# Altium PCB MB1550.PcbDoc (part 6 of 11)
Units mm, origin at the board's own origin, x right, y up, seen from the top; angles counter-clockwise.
Board outline 154.81 x 170.69 mm, 6 copper layers (Top Layer, Signal Layer 1, Signal Layer 2, Signal Layer 3, Signal Layer 4, Bottom Layer), stack 1.49 mm thick; 810 components, 633 nets, 2973 pads, 2150 vias.
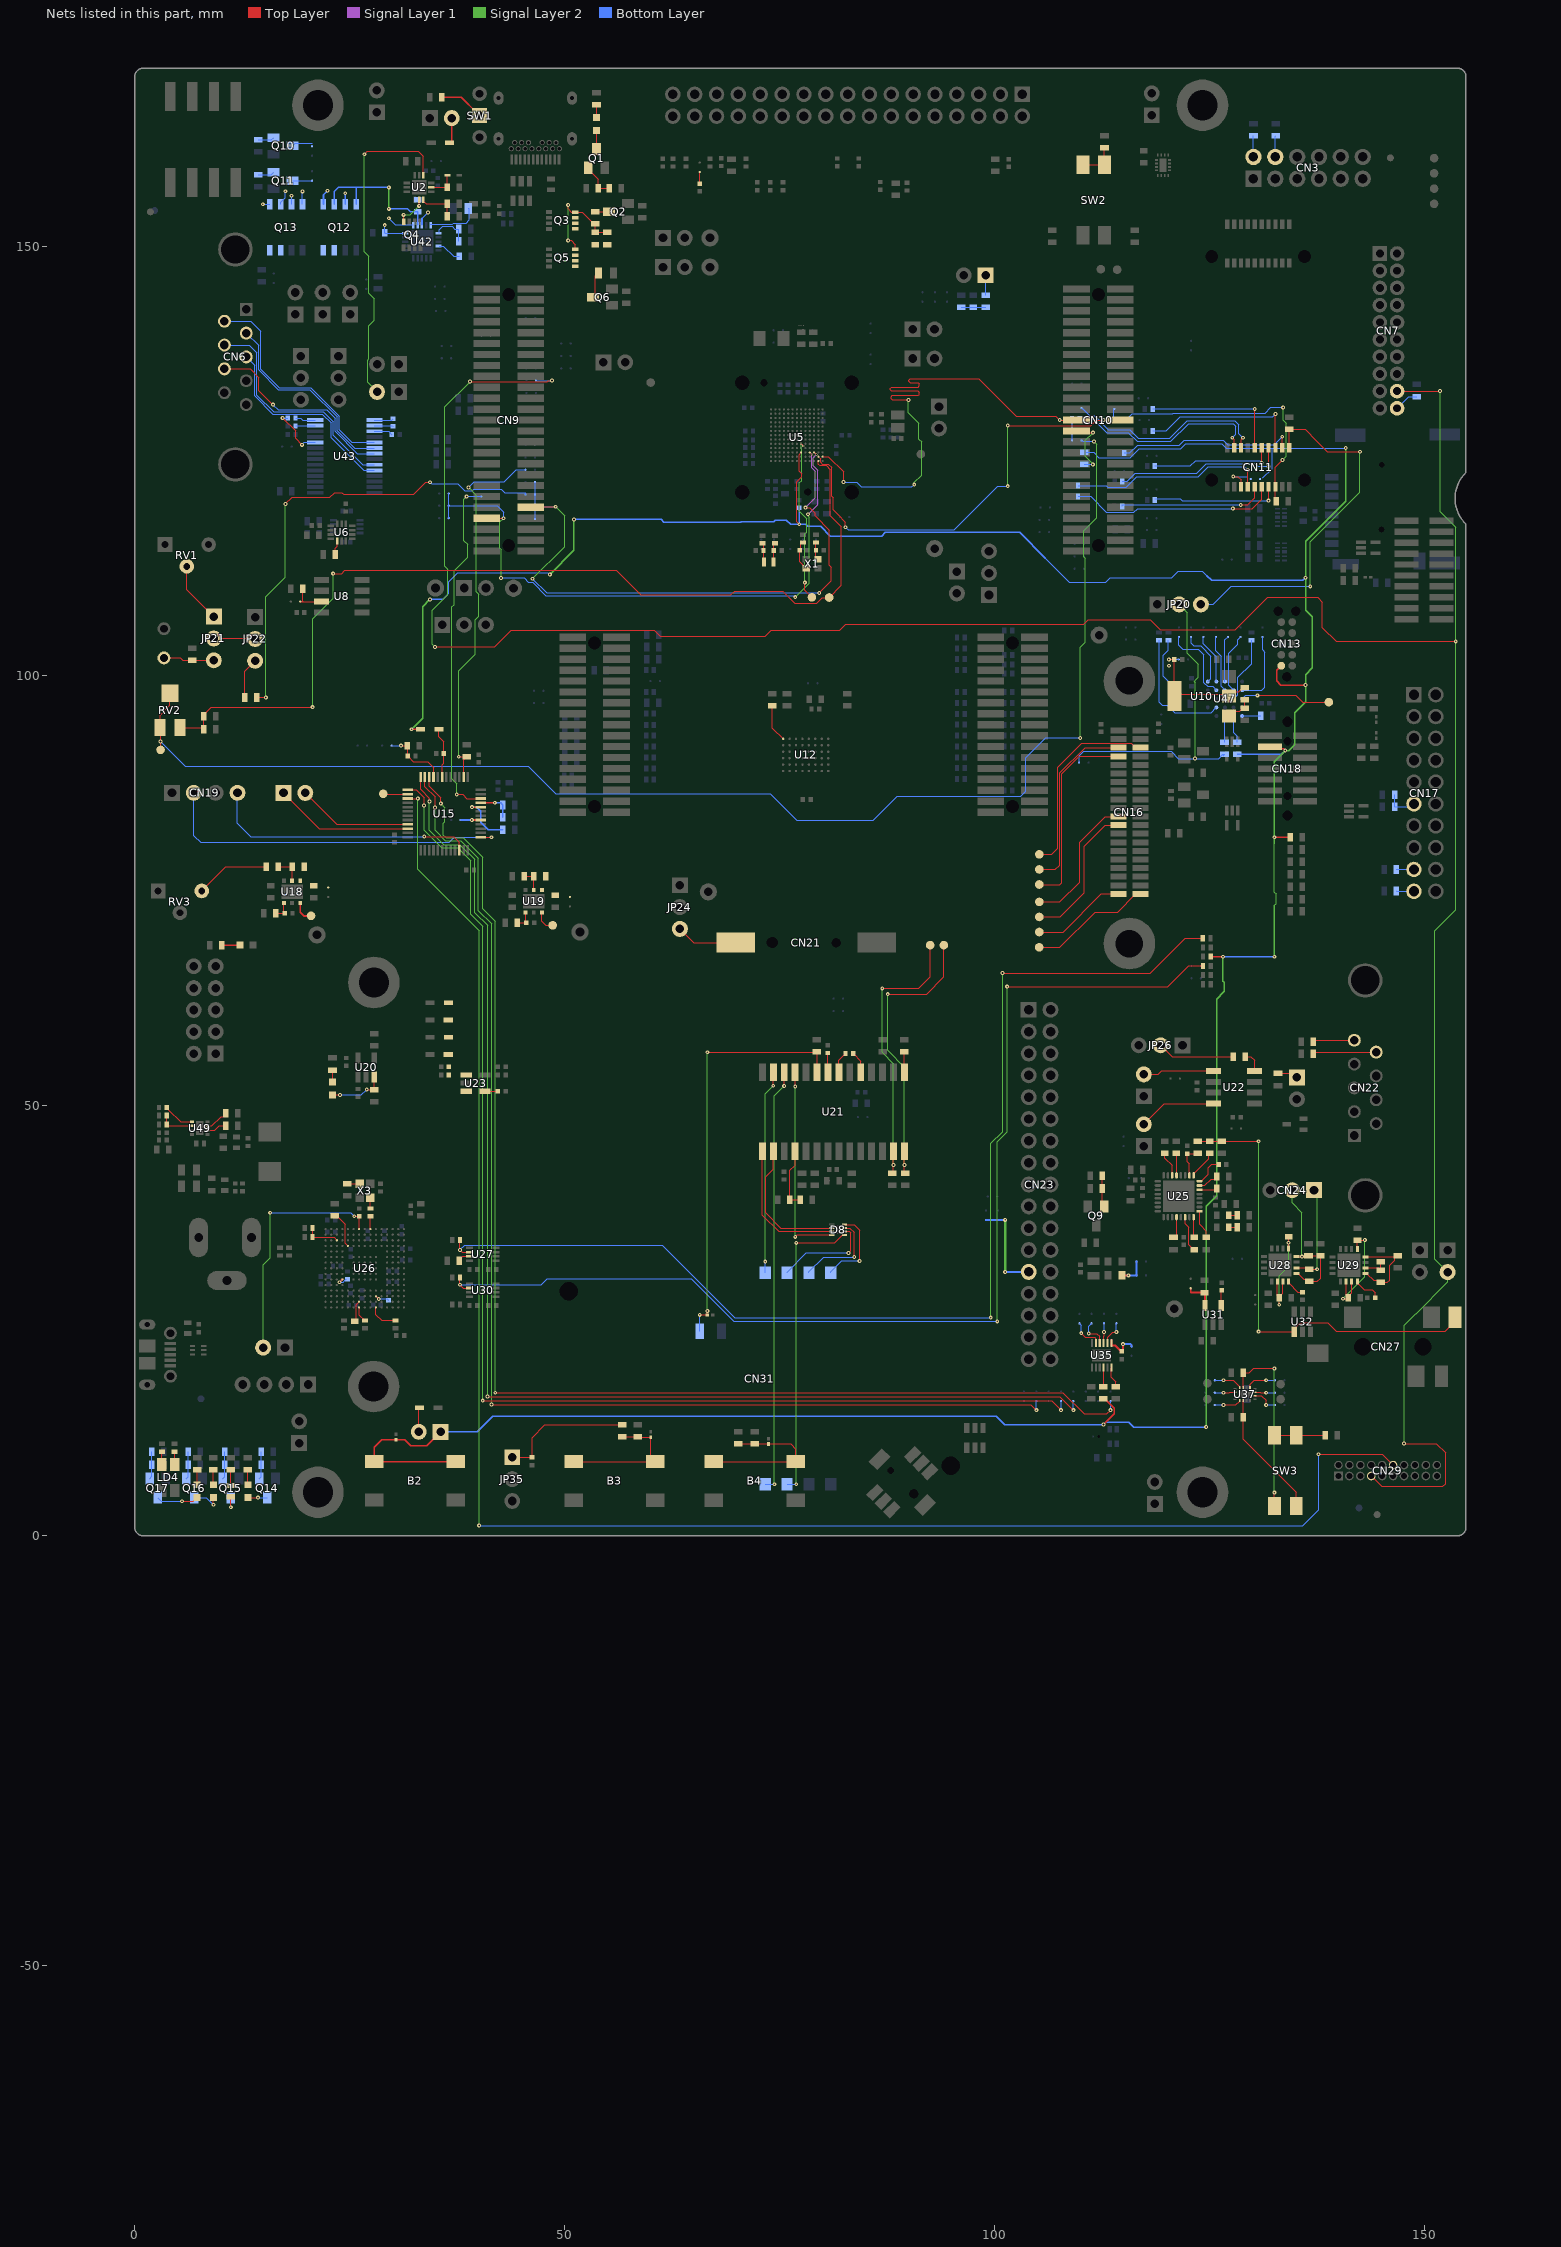
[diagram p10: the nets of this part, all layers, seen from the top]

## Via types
v1: diameter 0.45, hole 0.2, Top Layer to Bottom Layer, tented both sides, 1777 vias
v2: diameter 0.25, hole 0.1, Top Layer to Signal Layer 1, tented top, 344 vias
v3: diameter 0.25, hole 0.1, Signal Layer 1 to Signal Layer 2, 29 vias

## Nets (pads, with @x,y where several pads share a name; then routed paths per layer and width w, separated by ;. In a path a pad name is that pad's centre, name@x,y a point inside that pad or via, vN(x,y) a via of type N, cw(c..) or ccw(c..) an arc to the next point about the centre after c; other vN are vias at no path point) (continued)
MDF1_SDIN5: CN7.19 CN29.7 JP31.2 SB41.2 | length 321
  Top Layer w0.1: CN7.19@146.8,133.128 148.1,133.128
  Top Layer w0.12: v1(34.925,103.375) 41.875,103.375 43.803,105.303 60.422,105.303 61.125,104.6 73.3,104.6 73.995,105.295 81.97,105.295 82.665,105.99 110.365,105.99 110.9,106.525 118.1,106.525 119.27,105.355 127.976,105.355 131.783,109.162 137.563,109.162 138.125,108.6 138.125,105.627 139.727,104.025 v1(153.625,104.025) ; v1(38.99,134.24) 47.99,134.24 48.1,134.35 v1(48.525,134.35) ; CN29.7@143.795,6.965 144.992,5.768 152.128,5.768 152.44,6.08 152.44,9.646 151.343,10.743 v1(147.604,10.743) ; 148.1,133.128 v1(151.8,133.128)
  Signal Layer 2 w0.12: v1(34.925,103.375) 34.625,103.675 34.625,107.65 36.416,109.441 36.416,112.409 36.075,112.75 36.075,131.325 v1(38.99,134.24) ; v1@147.605,10.742 147.605,24.476 148.984,25.855 149.003,25.855 152.675,29.527 JP31.2@152.675,30.68 151.2,32.155 151.2,70.4 153.625,72.825 v1(153.625,104.025) 153.625,117.3 151.8,119.125 v1(151.8,133.128)
  Bottom Layer w0.12: SB41.2@46.65,134.35 v1(48.525,134.35)
MEMS_1-2_SEL: R118.1 SW3.1 U37.3 | length 21.5
  Top Layer w0.12: U37.3@128.9,17.275 R118.1@128.9,18.975 129.625,18.975 130.12,19.47 v1(132.53,19.47) ; SW3.1@132.53,3.475 v1(132.53,5.03)
  Signal Layer 2 w0.12: v1(132.53,5.03) v1(132.53,19.47)
MEMS_3-4_SEL: R122.1 SW3.2 U37.10 | length 14.8
  Top Layer w0.12: U37.10@128.9,15.725 R122.1@128.9,13.8 128.9,11.225 135.07,5.055 SW3.2@135.07,3.475
MEMS_LED: CN29.12 U15.15 | length 202.7
  Top Layer w0.12: U15.15@31.748,85.75 v1(32.925,85.75) ; v1(137.664,9.493) 145.077,9.493 CN29.12@146.335,8.235
  Signal Layer 2 w0.12: v1(32.925,85.75) 32.925,77.525 40.05,70.4 v1(40.05,1.2)
  Bottom Layer w0.12: v1(40.05,1.2) 135.843,1.2 137.664,3.021 v1(137.664,9.493)
MFX_I2C_ADDR: R231.2 R233.2 U15.45 | length 4.1
  Top Layer w0.2: U15.45@40.248,85.25 v1(41.875,85.25)
  Bottom Layer w0.2: v1(41.875,85.25) 42.55,85.25 R231.2@42.8,85 R233.2@42.8,83.575
MFX_IRQ_OUT: SB70.2 U15.46 | length 40.7
  Top Layer w0.12: v1(37.45,86.225) 38.125,86.225 38.6,85.75 U15.46@40.248,85.75
  Signal Layer 2 w0.12: v1(37.45,86.225) 37.45,87.45 36.865,88.035 36.865,108.042 37.13,108.307 37.13,112.23 38.702,113.802 38.702,115.29 38.25,115.742 38.25,120.525 v1(38.6,120.875)
  Bottom Layer w0.12: v1(38.6,120.875) SB70.2@40.3,120.875
MFX_LOOP: TP19.1 U15.14 | length 2.9
  Top Layer w0.12: TP19.1@28.9,86.3 28.95,86.25 U15.14@31.748,86.25
MFX_SWCLK: CN19.2 U15.37 | length 41.4
  Top Layer w0.12: U15.37@40.248,81.25 v1(41.475,81.25)
  Bottom Layer w0.12: CN19.2@6.869,86.411 6.869,81.431 7.65,80.65 36.575,80.65 37.175,81.25 v1(41.475,81.25)
MFX_SWDIO: CN19.4 U15.34 | length 31.2
  Top Layer w0.12: v1(33.675,81.325) 37.075,81.325 37.748,80.652 U15.34@37.748,79.75
  Bottom Layer w0.12: CN19.4@11.949,86.411 11.949,82.851 13.475,81.325 v1(33.675,81.325)
MFX_TSC_XN: SB142.2 U15.11 | length 141.9
  Top Layer w0.12: U15.11@33.748,88.25 33.748,87.127 34.925,85.95 v1(34.925,84.7) ; v1(41.5,15.275) 104.2,15.275 v1(104.85,14.625)
  Signal Layer 2 w0.12: v1(34.925,84.7) 34.925,82.05 36.125,80.85 37.925,80.85 39.975,78.8 39.975,72.725 41.5,71.2 v1(41.5,15.275)
  Bottom Layer w0.12: v1(104.85,14.625) SB142.2@104.85,15.675
MFX_TSC_XP: SB136.2 U15.10 | length 149.9
  Top Layer w0.12: U15.10@34.248,88.25 34.248,87.202 35.6,85.85 v1(35.6,85.175) ; v1(41.925,16.65) 107.925,16.65 110.4,14.175 113.025,14.175 v1(113.475,14.625)
  Signal Layer 2 w0.12: v1(35.6,85.175) 36.08,84.695 36.08,83.052 35.895,82.867 35.895,81.505 36.2,81.2 38.223,81.2 40.475,78.948 40.475,72.925 41.925,71.475 v1(41.925,16.65)
  Bottom Layer w0.12: v1(113.475,14.625) SB136.2@113.475,15.675
MFX_TSC_YN: SB140.2 U15.13 | length 145.1
  Top Layer w0.12: U15.13@31.748,86.75 32.725,86.75 33.65,85.825 v1(33.65,84.95) ; v1(40.475,15.725) 106.625,15.725 v1(107.725,14.625)
  Signal Layer 2 w0.12: v1(33.65,84.95) 33.65,82.075 35.725,80 37.575,80 39.088,78.487 39.088,72.262 40.475,70.875 v1(40.475,15.725)
  Bottom Layer w0.12: v1(107.725,14.625) SB140.2@107.725,15.675
MFX_TSC_YP: SB139.2 U15.12 | length 146.2
  Top Layer w0.12: U15.12@33.248,88.25 33.248,86.827 34.275,85.8 v1(34.275,85.4) ; v1(41.025,16.2) 107.575,16.2 v1(109.15,14.625)
  Signal Layer 2 w0.12: v1(34.275,85.4) 34.275,82.075 35.95,80.4 37.8,80.4 39.538,78.662 39.538,72.487 41.025,71 v1(41.025,16.2)
  Bottom Layer w0.12: v1(109.15,14.625) SB139.2@109.15,15.675
MFX_WAKEUP: R45.2 SB60.2 U15.2 | length 43.7
  Top Layer w0.12: v1(37.675,90.6) R45.2@38.6,90.6 38.248,90.248 U15.2@38.248,88.25
  Signal Layer 2 w0.12: v1(37.675,90.6) 37.675,100.625 39.58,102.53 39.58,106.534 39.981,106.934 39.981,109.527 39.74,109.767 39.74,121.01 v1(38.825,121.925)
  Bottom Layer w0.12: v1(38.825,121.925) 39.475,122.575 42.975,122.575 44.375,123.975 SB60.2@45.45,123.975
MIC_IN: C66.1 CN27.2 R83.1 R84.2 U32.1 | length 54.1
  Top Layer w0.12: R83.1@123.6,45.9 C66.1@125,45.9 R84.2@126.4,45.9 v1(130.7,45.9) ; v1(130.7,23.75) U32.1@134.85,23.75 134.85,24.1 135.55,24.8 138.725,24.8 139.725,23.8 152.425,23.8 153.55,24.925 CN27.2@153.55,25.45
  Signal Layer 2 w0.12: v1(130.7,23.75) v1(130.7,45.9)
NetB3_3: B3.3 B3.4 R123.2 R124.2 U39.1 | length 15.9
  Top Layer w0.12: B3.4@51.05,8.641 B3.3@60.55,8.641 60,9.191 U39.1@60,11.487 58.513,11.487 R124.2@58.5,11.5 R123.2@56.7,11.5
NetB4_3: B4.3 B4.4 R125.2 R126.2 U41.1 | length 17.9
  Top Layer w0.12: B4.4@67.35,8.641 B4.3@76.85,8.641 76.85,10.1 76.263,10.687 U41.1@73.7,10.687 72.113,10.687 R126.2@72.1,10.7 R125.2@70.2,10.7
NetC16_2: C16.2 SB1.2 | length 1.4
  Top Layer w0.12: C16.2@65.7,157.25 SB1.2@65.7,158.6
NetC17_1: C17.1 D2.2 U2.8 | length 3.2
  Top Layer w0.12: U2.8@34.5,156.825 C17.1@36.325,156.825 36.325,158.175 D2.2@36.375,158.225
NetC19_1: C19.1 Q3.4 Q5.4 R14.2 R18.1 | length 12.5
  Top Layer w0.12: v1(50.4,150.65) 50.75,150.65 51.225,150.175 Q5.4@51.225,149.6 ; v1(50.4,154.775) 50.4,154.325 50.775,153.95 Q3.4@51.225,153.95 52.025,153.95 R14.2@53.375,152.6 ; R14.2@53.35,152.6 R14.2@53.375,152.6 ; R18.1@54.95,151.575 C19.1@53.55,151.575 R14.2@53.55,152.6 R14.2@53.375,152.6
  Signal Layer 2 w0.12: v1(50.4,150.65) v1(50.4,154.775)
NetC19_2: C19.2 Q3.1 Q3.2 Q3.3 Q5.1 Q5.2 Q5.3 R18.2
NetC34_2: C34.2 R35.2 SB104.1 U10.2 U10.4 | length 14.9
  Top Layer w0.12: v1(120.255,101.925) C34.2@120.9,101.925 U10.4@120.9,97.65 121.125,97.875 127.025,97.875 U10.2@127.25,97.65 127.75,98.15 128.4,98.15 128.875,98.625 R35.2@129.1,98.625
  Bottom Layer w0.12: v1(120.255,101.925) SB104.1@121.4,101.925
  other v1: 120.275,101.187
NetC39_2: C39.2 C42.2 SB110.2 U15.9 | length 7.7
  Top Layer w0.12: v1(30.975,91.9) C39.2@31.7,91.9 31.75,91.85 C42.2@31.75,90.7 32.4,90.05 34.05,90.05 34.748,89.352 U15.9@34.748,88.25
  Bottom Layer w0.12: SB110.2@29.875,91.9 v1(30.975,91.9)
NetC40_1: C40.1 D3.1 U15.7 | length 5.9
  Top Layer w0.12: D3.1@35.37,93.8 35.37,92.93 35.95,92.35 C40.1@35.95,91 35.95,89.85 35.748,89.648 U15.7@35.748,88.25
NetC47_2: C47.2 R56.2 SB3.1 U18.4
NetC49_2: C49.2 R59.2 SB4.1 U19.4
NetC50_1: C50.1 R64.2 U18.1 | length 2.3
  Top Layer w0.12: R64.2@16.4,72.4 C50.1@17.45,72.4 17.35,72.5 U18.1@17.35,73.6
NetC51_1: C51.1 R65.2 U19.1 | length 2.3
  Top Layer w0.12: R65.2@44.5,71.3 C51.1@45.55,71.3 45.45,71.4 U19.1@45.45,72.5
NetC52_1: C52.1 U21.8 | length 2.2
  Top Layer w0.13: C52.1@80.6,56.15 80.615,56.135 U21.8@80.615,53.931
NetC53_1: C53.1 U21.5 | length 2.5
  Top Layer w0.13: C53.1@83.55,56.1 84.425,55.225 U21.5@84.425,53.931
NetC53_2: C53.2 U21.7 | length 2.5
  Top Layer w0.13: U21.7@81.885,53.931 81.885,55.285 82.65,56.05 C53.2@82.65,56.1
NetC55_1: C55.1 C57.2 D4.2 D5.2 D6.2 D7.2 U23.1 U23.3
NetC62_2: C62.2 U23.4 | length 1.5
  Top Layer w0.12: U23.4@40.75,51.7 C62.2@42.225,51.7
NetC65_1: C65.1 U25.22 | length 2.9
  Top Layer w0.12: C65.1@119.8,44.5 119.8,43.925 120.65,43.075 U25.22@120.65,41.925
NetC66_2: C66.2 U25.17 | length 3.3
  Top Layer w0.12: U25.17@123.15,41.925 123.15,42.1 124.9,43.85 124.9,44.4 C66.2@125,44.5
NetC67_1: C67.1 U25.21 | length 2.6
  Top Layer w0.12: C67.1@121.1,44.5 121.15,44.45 U25.21@121.15,41.925
NetC68_1: C68.1 R83.2 U25.18 | length 3.8
  Top Layer w0.12: U25.18@122.65,41.925 122.65,43.25 122.4,43.5 C68.1@122.4,44.45 123.55,44.45 R83.2@123.6,44.5
NetC69_2: C69.2 U25.16 | length 3.5
  Top Layer w0.12: U25.16@123.825,41.25 124.025,41.25 124.85,42.075 124.85,42.8 125.25,43.2 C69.2@126.05,43.2
NetC72_2: C72.2 U25.15 | length 2.6
  Top Layer w0.12: U25.15@123.825,40.75 124.45,40.75 125.175,41.475 125.8,41.475 C72.2@125.8,41.8
NetC76_2: C76.2 U25.14 | length 2
  Top Layer w0.12: U25.14@123.825,40.25 125.65,40.25 C76.2@125.8,40.4
NetC83_1: C83.1 JP32.2 U26.J1 | length 28
  Top Layer w0.1: v1(25.525,37.175) C83.1@26.1,37.175 U26.J1@26.1,35.675
  Signal Layer 2 w0.12: JP32.2@14.93,21.9 14.93,31.505 15.75,32.325 v1(15.75,37.575)
  Bottom Layer w0.1: 19.325,37.575 25.125,37.575 v1(25.525,37.175)
  Bottom Layer w0.12: v1(15.75,37.575) 19.325,37.575
NetC84_1: C84.1 R98.2 | length 1
  Top Layer w0.12: C84.1@127.2,37.3 R98.2@128.2,37.3
NetC85_2: C85.2 C101.1 U28.2 U28.3 U28.9 | length 14
  Top Layer w0.12: U28.2@132.875,29.6 132.875,27.925 C101.1@133.1,27.7 ; v1(133.1,26.875) C101.1@133.1,27.7 ; U28.3@133.525,29.6 133.525,28.225 133.1,27.8 C101.1@133.1,27.7 ; U28.9@134.175,33.4 v1(134.175,34.087) 134.175,34.775 C85.2@134.2,34.8
  Signal Layer 2 w0.12: v1(133.1,26.875) 133.1,30.275 134.175,31.35 v1(134.175,34.087)
NetC86_1: C86.1 R99.2 | length 1
  Top Layer w0.12: C86.1@127.2,35.9 R99.2@128.2,35.9
NetC87_1: C87.1 C102.1 U29.2 U29.3 U29.9 | length 14.4
  Top Layer w0.12: v1(140.5,27.575) 140.975,27.575 C102.1@141.1,27.7 ; U29.2@140.875,29.58 140.875,27.925 C102.1@141.1,27.7 ; U29.3@141.525,29.58 141.525,28.3 141.1,27.875 C102.1@141.1,27.7 ; U29.9@142.175,33.38 142.175,34.375 C87.1@142.2,34.4 v1(143.05,34.4)
  Signal Layer 2 w0.12: v1(140.5,27.575) 143.05,30.125 v1(143.05,34.4)
NetC88_1: C88.1 U25.8 | length 2.4
  Top Layer w0.12: U25.8@123.15,37.075 123.15,34.75 C88.1@123.2,34.7
NetC88_2: C88.2 U25.6 | length 4.3
  Top Layer w0.12: U25.6@122.15,37.075 122.15,36.3 122.55,35.9 122.55,33.875 123.125,33.3 C88.2@123.2,33.3
NetC89_2: C89.2 U25.9 | length 3.4
  Top Layer w0.12: U25.9@123.825,37.75 123.825,36.225 124.6,35.45 C89.2@124.6,34.7
NetC91_2: C91.2 CN24.2 R105.2 R111.1 U28.5 U28.8 | length 17
  Top Layer w0.12: U28.5@135.1,30.525 135.275,30.525 135.95,29.85 136.35,29.85 R111.1@136.6,29.6 137.525,29.6 137.905,29.98 137.905,32.6 C91.2@137.9,32.6 R105.2@136.5,32.6 136.375,32.475 v1(135.738,32.475) U28.8@135.1,32.475
  Signal Layer 2 w0.12: CN24.2@134.6,40.2 134.6,38.725 135.738,37.587 v1(135.738,32.475)
NetC96_2: C96.2 SB7.1 U31.5 | length 3.6
  Top Layer w0.2: SB7.1@122.8,28.8 122.8,28.3 C96.2@124.4,28.3 124.45,28.25 U31.5@124.45,26.8
NetC97_2: C97.2 U31.4 | length 1.8
  Top Layer w0.12: U31.4@126.35,26.8 126.35,28.5 C97.2@126.4,28.55
NetC98_1: C98.1 U28.4 | length 2.2
  Top Layer w0.12: U28.4@134.175,29.6 134.175,29.425 135.25,28.35 C98.1@135.8,28.35
NetC103_2: C103.2 U29.4 | length 3.3
  Top Layer w0.12: U29.4@142.175,29.58 142.175,29.45 143,28.625 143.925,28.625 144.25,28.3 C103.2@144.25,27.7
NetC106_2: C106.2 U26.J14 | length 2.5
  Top Layer w0.09: C106.2@25.575,24.975 25.775,25.175 25.775,26.9 U26.J14@26.1,27.225
NetC110_1: C110.1 SB133.1 U35.1 | length 4.2
  Top Layer w0.25: U35.1@113.575,22.75 U35.1@113.575,22.425 113.575,22.175 113.625,22.125 114.05,22.125 114.725,21.45 C110.1@114.775,21.45 114.925,21.6 v1(114.925,22.3)
  Bottom Layer w0.25: v1(114.925,22.3) 115.8,22.3 115.925,22.175 SB133.1@115.925,22.05
NetC111_2: C111.2 JP35.1 R123.1 | length 15.7
  Top Layer w0.12: JP35.1@43.9,9.14 43.915,9.125 C111.2@46.2,9.125 46.2,11.44 47.66,12.9 R123.1@56.7,12.9
NetC114_1: C114.1 Q12.2 Q12.4 U42.7 | length 17.5
  Signal Layer 2 w0.2: v1(29.55,154.325) v1(29.55,156.825)
  Bottom Layer w0.2: Q12.2@23.215,154.85 23.215,156.34 23.7,156.825 25.775,156.825 ; Q12.4@25.755,154.85 25.755,156.805 25.775,156.825 ; v1(29.55,154.325) 31.725,154.325 32.075,153.975 C114.1@32.9,153.975 U42.7@32.9,152.5 ; v1(29.55,156.825) 25.775,156.825
NetC114_2: C114.2 Q12.7 Q12.8 Q13.7 Q13.8 R138.2 U42.10 | length 6.2
  Bottom Layer w0.12: U42.10@34.4,152.5 34.4,152.515 36.94,152.515 37.08,152.655 38.528,152.655 38.905,153.032 38.905,154.375 R138.2@38.8,154.375
NetC115_1: C115.1 Q13.2 Q13.4 U42.5 | length 6.5
  Bottom Layer w0.12: Q13.2@16.965,154.85 16.965,155.09 17.516,155.641 v1(17.516,156.374) ; Q13.4@19.505,154.85 v1(19.505,156.355) ; v1(29.075,152.425) C115.1@29.075,151.525 29.1,151.5 U42.5@31.4,151.5
NetC116_1: C116.1 U42.14 | length 2.8
  Bottom Layer w0.12: U42.14@35.4,150 35.9,150 37.1,148.8 C116.1@37.725,148.8
NetC117_2: C117.2 R143.1 R144.1 | length 2.9
  Bottom Layer w0.12: R144.1@96.1,142.9 C117.2@97.525,142.9 R143.1@98.975,142.9
NetC125_1: C125.1 U43.24 | length 6.3
  Top Layer w0.12: v1(17.2,130) 18.7,128.5 18.7,127.625 v1(19.45,126.875)
  Bottom Layer w0.12: v1(17.2,130) C125.1@17.8,130 ; v1(19.45,126.875) 19.736,127.161 U43.24@20.976,127.161
NetC125_2: C125.2 U43.28 | length 2.4
  Bottom Layer w0.12: C125.2@18.7,130 19.325,130 19.564,129.761 U43.28@20.976,129.761
NetC126_1: C126.1 U43.1 | length 2.2
  Bottom Layer w0.12: U43.1@27.876,129.761 29.886,129.761 C126.1@30.05,129.925
NetC126_2: C126.2 U43.2 | length 2.2
  Bottom Layer w0.12: U43.2@27.876,129.111 29.964,129.111 C126.2@30.05,129.025
NetC127_2: C127.2 U43.27 | length 2.3
  Bottom Layer w0.12: C127.2@18.7,129.075 18.736,129.111 U43.27@20.976,129.111
NetC132_2: C132.2 U43.3 | length 2.2
  Bottom Layer w0.12: U43.3@27.876,128.461 29.514,128.461 C132.2@29.9,128.075
NetC171_2: C171.2 U26.M10 | length 1.4
  Top Layer w0.2: v1(23.825,29.5) U26.M10@24.15,29.825
  Bottom Layer w0.1: v1(23.825,29.5) 24.225,29.5 24.55,29.825 C171.2@24.6,29.825
NetC177_2: C177.2 U26.F13 | length 1.6
  Top Layer w0.2: U26.F13@28.05,27.875 v1(28.375,27.55)
  Bottom Layer w0.1: v1(28.375,27.55) 29.363,27.55 C177.2@29.493,27.42
NetC189_2: C189.2 U49.1 | length 3.6
  Top Layer w0.12: C189.2@3.726,49.817 3.921,49.622 3.921,49.582 5.326,48.177 U49.1@6.671,48.177
NetCN3_7: CN3.7 R135.1 | length 2.4
  Bottom Layer w0.12: CN3.7@130.1,160.361 R135.1@130.1,162.8
NetCN3_8: CN3.8 R134.1 | length 2.5
  Bottom Layer w0.12: CN3.8@132.64,160.361 132.64,162.74 R134.1@132.7,162.8
NetCN6_2: CN6.2 U43.6 | length 23
  Bottom Layer w0.12: CN6.2@12.97,139.87 14.408,138.432 14.408,135.592 16.7,133.3 20.38,133.3 23.555,130.125 23.555,128.531 25.575,126.511 U43.6@27.876,126.511
NetCN6_3: CN6.3 U43.10 | length 23.5
  Bottom Layer w0.12: CN6.3@12.97,137.1 13.928,136.142 13.928,132.572 16.04,130.46 21.815,130.46 22.835,129.44 22.835,127.69 26.614,123.911 U43.10@27.876,123.911
NetCN6_6: CN6.6 U43.5 | length 26.8
  Bottom Layer w0.12: CN6.6@10.43,141.255 13.47,141.255 14.648,140.077 14.648,135.691 16.799,133.54 20.479,133.54 23.795,130.224 23.795,128.63 25.264,127.161 U43.5@27.876,127.161
NetCN6_7: CN6.7 U43.9 | length 27
  Bottom Layer w0.12: CN6.7@10.43,138.485 13.3,138.485 14.168,137.617 14.168,132.671 16.139,130.7 21.914,130.7 23.075,129.539 23.075,127.975 26.489,124.561 U43.9@27.876,124.561
NetCN6_8: CN6.8 U43.7 | length 23.3
  Top Layer w0.12: CN6.8@10.43,135.715 13.41,135.715 14.45,134.675 14.45,133.175 v1(16.075,131.55)
  Bottom Layer w0.12: v1(16.075,131.55) 16.685,130.94 22.35,130.94 23.315,129.975 23.315,128.431 25.885,125.861 U43.7@27.876,125.861
NetCN7_20: CN7.20 R146.2 | length 2.9
  Bottom Layer w0.12: CN7.20@146.8,131.128 148.172,132.5 R146.2@149.1,132.5
NetCN8_1: CN8.1 R143.2 | length 2.3
  Bottom Layer w0.12: CN8.1@98.945,146.6 98.975,146.57 R143.2@98.975,144.3
NetCN10_27: CN10.27 R156.2 | length 7.5
  Top Layer w0.127: CN10.27@109.523,128.495 109.718,128.3 v1(111.45,128.3)
  Signal Layer 2 w0.12: v1(111.425,124.6) 111.425,124.7 110.549,125.576 110.549,127.399 v1(111.45,128.3)
  Bottom Layer w0.12: R156.2@110.4,124.6 v1(111.425,124.6)
NetCN16_1: CN16.1 TP33.1 | length 14.3
  Top Layer w0.12: TP33.1@105.175,68.45 107.6,68.45 111.7,72.55 114.325,72.55 116.43,74.655 CN16.1@116.95,74.655
NetCN16_2: CN16.2 TP30.1 | length 11
  Top Layer w0.12: TP30.1@105.2,70.225 107.975,70.225 112.405,74.655 CN16.2@114.4,74.655
NetCN16_18: CN16.18 TP26.1 | length 16.8
  Top Layer w0.12: TP26.1@105.2,71.975 107.625,71.975 110.425,74.775 110.425,80.225 112.855,82.655 CN16.18@114.4,82.655
NetCN16_20: CN16.20 TP24.1 | length 16.1
  Top Layer w0.12: TP24.1@105.2,73.725 107.6,73.725 109.875,76 109.875,80.675 112.855,83.655 CN16.20@114.4,83.655
NetCN16_34: CN16.34 TP22.1 | length 22.8
  Top Layer w0.12: TP22.1@105.2,75.75 107.6,75.75 107.825,75.975 107.825,88.621 109.859,90.655 CN16.34@114.4,90.655
NetCN16_35: CN16.35 TP20.1 | length 22.6
  Top Layer w0.1: 113.075,92.155 115.87,92.155 116.37,91.655 CN16.35@116.75,91.655
  Top Layer w0.12: TP20.1@105.2,79.25 106.626,79.25 107.345,79.969 107.345,89.37 110.13,92.155 113.075,92.155
NetCN16_36: CN16.36 TP21.1 | length 21.3
  Top Layer w0.12: TP21.1@105.2,77.5 107.075,77.5 107.585,78.01 107.585,88.721 110.519,91.655 CN16.36@114.4,91.655
NetCN17_11: CN17.11 R230.2 R232.1 | length 3.8
  Bottom Layer w0.12: R230.2@146.5,86.2 R232.1@146.5,84.8 148.44,84.8 CN17.11@148.76,85.12
NetCN17_17: CN17.17 R235.2 | length 2.1
  Bottom Layer w0.12: R235.2@146.7,77.5 CN17.17@148.76,77.5
NetCN17_19: CN17.19 R236.2 | length 2.1
  Bottom Layer w0.12: R236.2@146.7,75 146.74,74.96 CN17.19@148.76,74.96
NetCN20_1: CN20.1 U15.22 | length 16.2
  Top Layer w0.12: CN20.1@17.3,86.4 21.45,82.25 U15.22@31.748,82.25
NetCN20_2: CN20.2 U15.21 | length 13.4
  Top Layer w0.12: CN20.2@19.84,86.4 23.49,82.75 U15.21@31.748,82.75
NetCN21_1: CN21.1 JP24.3 | length 7.1
  Top Layer w0.12: JP24.3@63.4,70.585 64.985,69 CN21.1@69.883,69
NetCN22_5: CN22.5 R77.2 | length 4.8
  Top Layer w0.12: R77.2@137.05,57.475 137.215,57.64 CN22.5@141.83,57.64
NetCN22_9: CN22.9 R78.2 | length 7.4
  Top Layer w0.12: R78.2@137.05,56.075 137.23,56.255 CN22.9@144.37,56.255
NetCN23_25: CN23.25 SB124.2 SB125.2 | length 11
  Signal Layer 2 w0.25: v1(101.225,30.7) v1(101.225,36.75)
  Bottom Layer w0.25: SB125.2@99,36.75 SB124.2@100.4,36.75 v1(101.225,36.75) ; v1(101.225,30.7) CN23.25@103.96,30.7
NetCN24_1: CN24.1 R111.2 U28.6 | length 11.8
  Top Layer w0.12: U28.6@135.1,31.175 136.425,31.175 R111.2@136.6,31 v1(137.5,31)
  Signal Layer 2 w0.12: CN24.1@137.14,40.2 137.5,39.84 v1(137.5,31)
NetCN31_C1: CN31.C1 D8.8 | length 9.6
  Top Layer w0.13: D8.8@82.55,36.2 83.65,36.2 84.3,35.55 v1(84.3,31.975)
  Bottom Layer w0.13: CN31.C1@80.94,30.6 80.94,30.715 82.2,31.975 v1(84.3,31.975)
NetCN31_C2: CN31.C2 D8.7 | length 10.3
  Top Layer w0.13: D8.7@82.55,35.8 83.175,35.8 83.675,35.3 v1(83.675,32.425)
  Bottom Layer w0.13: CN31.C2@78.4,30.6 78.4,30.7 80.125,32.425 v1(83.675,32.425)
NetCN31_C3: CN31.C3 D8.6 | length 11.4
  Top Layer w0.13: D8.6@82.55,35.4 83.1,35.4 83.25,35.25 83.25,33.15 v1(83,32.9)
  Bottom Layer w0.13: CN31.C3@75.86,30.6 75.86,30.685 78.075,32.9 v1(83,32.9)
NetCN31_C4: CN31.C4 U21.13 | length 23.7
  Top Layer w0.13: v1(74.25,52.35) 74.25,53.916 U21.13@74.265,53.931
  Signal Layer 2 w0.13: v1(73.32,31.895) 73.32,51.42 v1(74.25,52.35)
  Bottom Layer w0.102: CN31.C4@73.32,30.6 v1(73.32,31.895)
NetCN31_C7: CN31.C7 D8.5 | length 35.1
  Top Layer w0.13: v1(76.925,34.075) 81.4,34.075 82.325,35 D8.5@82.55,35
  Signal Layer 2 w0.13: v1(76.925,6) v1(76.925,34.075)
  Bottom Layer w0.13: CN31.C7@75.86,6 v1(76.925,6)
NetCN31_C8: CN31.C8 U21.12 | length 49.5
  Top Layer w0.13: v1(75.525,52.325) 75.525,53.921 U21.12@75.535,53.931
  Signal Layer 2 w0.13: v1(74.385,6) 74.379,6.006 74.379,51.179 v1(75.525,52.325)
  Bottom Layer w0.13: CN31.C8@73.32,6 v1(74.385,6)
NetCN31_S2: CN31.S2 R74.1 U21.9 U33.1 | length 48.3
  Top Layer w0.13: v1(65.7,25.7) U33.1@66.588,25.7 v1(66.588,26.163) ; v1(66.588,56.238) 79.238,56.238 79.345,56.13 U21.9@79.345,53.931
  Signal Layer 2 w0.13: v1(66.588,26.163) v1(66.588,56.238)
  Bottom Layer w0.13: CN31.S2@65.7,23.8 v1(65.7,25.7)
NetD1_2: D1.2 JP3.2 | length 3.1
  Top Layer w0.2: D1.2@36.62,162.025 36.87,162.025 JP3.2@36.87,164.875
NetD8_2: D8.2 U21.16 | length 15.9
  Top Layer w0.13: U21.16@74.265,44.751 74.265,42.614 73.392,41.74 73.392,37.549 75.141,35.8 D8.2@81.05,35.8
NetD8_3: D8.3 U21.15 | length 16.3
  Top Layer w0.13: U21.15@72.995,44.751 72.995,37.308 74.904,35.4 D8.3@81.05,35.4
NetD8_4: D8.4 U21.11 | length 23.5
  Top Layer w0.13: v1(76.805,34.775) 77.03,35 D8.4@81.05,35 ; v1(76.805,52.27) U21.11@76.805,53.931
  Signal Layer 2 w0.13: v1(76.805,34.775) v1(76.805,52.27)
NetD9_1: D9.1 JP34.2 | length 2.8
  Top Layer w0.12: JP34.2@33.03,12.1 33.03,14.8 D9.1@33.13,14.9
NetJP15_2: JP15.2 U2.10 | length 38.3
  Top Layer w0.12: v1(26.7,160.678) 27.047,161.025 32.975,161.025 33.575,160.425 U2.10@33.575,158.25
  Signal Layer 2 w0.12: v1(26.7,160.678) 26.7,149.35 27.24,148.81 27.24,144.49 27.855,143.875 27.855,141.36 27.225,140.73 27.225,136.868 27.075,136.718 27.075,134.14 JP15.2@28.18,133.035
NetJP21_1: JP21.1 RV1.2 | length 7.1
  Top Layer w0.12: RV1.2@6.055,112.745 6.055,110.045 JP21.1@9.2,106.9
NetJP21_2: JP21.2 JP22.2 | length 4.8
  Top Layer w0.12: JP21.2@9.2,104.36 13.94,104.36 JP22.2@14,104.3
NetJP21_3: JP21.3 R33.2 R34.2 | length 5.9
  Top Layer w0.12: R33.2@3.4,102.1 5.275,102.1 5.575,101.8 R34.2@6.7,101.8 6.72,101.82 JP21.3@9.2,101.82
NetJP22_3: JP22.3 R39.1 | length 4.8
  Top Layer w0.12: R39.1@12.8,97.5 12.8,100.56 JP22.3@14,101.76
NetJP26_2: JP26.2 R79.2 | length 9
  Top Layer w0.12: JP26.2@119.3,57.05 120.625,55.725 R79.2@127.725,55.725
NetJP27_2: JP27.2 U22.1 | length 8.3
  Top Layer w0.12: JP27.2@117.35,53.67 117.355,53.675 119.025,53.675 119.43,54.08 U22.1@125.475,54.08
NetJP28_1: JP28.1 R81.2 | length 2.4
  Top Layer w0.13: R81.2@132.95,53.775 134.69,53.775 JP28.1@135.15,53.315
NetJP29_2: JP29.2 U22.4 | length 9.1
  Top Layer w0.12: JP29.2@117.35,47.87 119.75,50.27 U22.4@125.475,50.27
NetL4_1: L4.1 SB127.2 SB128.2 | length 3.3
  Top Layer w0.25: L4.1@114.8,30.3 v1(115.55,30.3)
  Bottom Layer w0.25: v1(115.55,30.3) SB128.2@116.5,30.3 SB127.2@116.5,31.9
NetLD1_1: LD1.1 R1.1 | length 1.4
  Top Layer w0.12: LD1.1@53.7,164.95 R1.1@53.7,166.4
NetLD1_2: LD1.2 Q1.3 | length 2.1
  Top Layer w0.12: Q1.3@53.7,161.3 LD1.2@53.7,163.45
NetLD2_1: LD2.1 R67.2 | length 2.1
  Top Layer w0.2: R67.2@10.1,68.7 LD2.1@12.25,68.7
NetLD3_1: LD3.1 R80.1 | length 1.4
  Top Layer w0.102: LD3.1@23,52.775 R80.1@23,54.175
NetLD3_2: LD3.2 R82.1 U20.3 | length 6.6
  Top Layer w0.12: LD3.2@23,51.275 v1(23.875,51.275) ; v1(26.975,51.9) R82.1@27.85,51.9 U20.3@27.85,53.375
  Bottom Layer w0.12: v1(23.875,51.275) 26.35,51.275 v1(26.975,51.9)
NetLD4_2: LD4.2 R128.1 | length 1.5
  Top Layer w0.12: LD4.2@3.15,8.3 R128.1@3.15,9.8
NetLD4_3: LD4.3 R129.1 | length 1.5
  Top Layer w0.12: LD4.3@4.65,8.3 R129.1@4.65,9.8
NetLD5_1: LD5.1 R130.1 | length 1.7
  Top Layer w0.12: LD5.1@7.25,5.95 R130.1@7.25,7.7
NetLD5_2: LD5.2 Q17.3 | length 4.9
  Top Layer w0.12: v1(5.5,4.025) 6.825,4.025 LD5.2@7.25,4.45
  Bottom Layer w0.12: Q17.3@2.675,4.45 3.1,4.025 v1(5.5,4.025)
NetLD6_1: LD6.1 R131.1 | length 1.7
  Top Layer w0.12: LD6.1@9.15,5.95 R131.1@9.15,7.7
NetLD6_2: LD6.2 Q16.3 | length 3.4
  Top Layer w0.12: v1(9.15,3.625) LD6.2@9.15,4.45
  Bottom Layer w0.12: Q16.3@6.925,4.45 8.325,4.45 v1(9.15,3.625)
NetLD7_1: LD7.1 R132.1 | length 1.8
  Top Layer w0.12: LD7.1@11.15,5.85 R132.1@11.15,7.7
NetLD7_2: LD7.2 Q15.3 | length 2.4
  Top Layer w0.12: LD7.2@11.15,4.55 11.175,4.525 v1(11.175,3.325)
  Bottom Layer w0.12: v1(11.175,3.325) Q15.3@11.175,4.45
NetLD8_1: LD8.1 R133.1 | length 1.7
  Top Layer w0.12: LD8.1@13.15,5.95 R133.1@13.15,7.7
NetLD8_2: LD8.2 Q14.3 | length 2.3
  Top Layer w0.12: LD8.2@13.15,4.45 v1(14.325,4.45)
  Bottom Layer w0.12: v1(14.325,4.45) Q14.3@15.425,4.45
NetQ1_1: Q1.1 R8.2 R9.1 | length 4.2
  Top Layer w0.12: Q1.1@52.75,159.1 52.75,158.9 53.9,157.75 R8.2@53.9,156.7 R9.1@55.2,156.7
NetQ2_3: Q2.3 R14.1 | length 1.6
  Top Layer w0.12: R14.1@53.55,154 Q2.3@55.175,154
NetQ4_4: Q4.4 U2.5 | length 3.8
  Top Layer w0.12: Q4.4@31.275,152.825 v1(31.275,153.625) ; v1(33.075,154.675) U2.5@33.075,155.4
  Signal Layer 2 w0.12: v1(31.275,153.625) 32.025,153.625 v1(33.075,154.675)
NetQ6_3: Q6.3 R19.1 | length 3.1
  Top Layer w0.12: Q6.3@53.3,144.05 53.575,144.325 53.575,146.525 R19.1@53.925,146.875
NetQ9_1: Q9.1 R91.2 R93.2 | length 3.7
  Top Layer w0.12: R91.2@112.5,41.9 R93.2@112.5,40.4 112.5,38.55 Q9.1@112.75,38.3
NetQ10_2: Q10.2 R136.1 | length 1.9
  Bottom Layer w0.12: R136.1@14.375,162.338 15.9,162.338 Q10.2@16.15,162.588
NetQ10_3: Q10.3 SB9.1 | length 2.4
  Bottom Layer w0.12: Q10.3@18.35,161.638 18.662,161.95 20.625,161.95
NetQ11_2: Q11.2 R137.2 | length 1.9
  Bottom Layer w0.12: R137.2@14.375,158.313 15.9,158.313 Q11.2@16.15,158.563
NetQ11_3: Q11.3 SB12.2 | length 2.3
  Bottom Layer w0.12: Q11.3@18.35,157.613 18.363,157.6 SB12.2@20.625,157.6
NetQ12_1: Q12.1 Q12.3 U42.8 | length 4.7
  Bottom Layer w0.2: Q12.1@21.945,154.85 21.945,155.945 v1(22.425,156.425) ; Q12.3@24.485,154.85 v1(24.485,156.135) ; U42.8@33.4,152.5 33.4,153.2 v1(34.1,153.9)
NetQ13_1: Q13.1 Q13.3 U42.6 | length 4.9
  Bottom Layer w0.12: v1(14.9,154.85) Q13.1@15.695,154.85 ; Q13.3@18.235,154.85 v1(18.235,155.848) ; v1(29.55,153.225) 30.275,152.5 U42.6@32.4,152.5
NetQ14_1: Q14.1 R237.2 R241.2 | length 3.2
  Bottom Layer w0.12: Q14.1@14.475,6.65 14.725,6.9 R241.2@14.725,8.275 R237.2@14.725,9.775
NetQ15_1: Q15.1 R238.2 R242.2 | length 3.2
  Bottom Layer w0.12: Q15.1@10.225,6.65 10.475,6.9 R242.2@10.475,8.275 R238.2@10.475,9.775
NetQ16_1: Q16.1 R239.2 R243.2 | length 3.2
  Bottom Layer w0.12: Q16.1@5.975,6.65 6.225,6.9 R243.2@6.225,8.275 R239.2@6.225,9.775
NetQ17_1: Q17.1 R240.2 R244.2 | length 3.2
  Bottom Layer w0.12: Q17.1@1.725,6.65 2,6.925 R244.2@2,8.275 R240.2@2,9.775
NetR2_1: R2.1 SW1.1 | length 5.1
  Top Layer w0.2: R2.1@35.725,167.3 37.975,167.3 39.8,165.475 SW1.1@39.8,165.16
NetR3_1: R3.1 SW2.3 SW2.4 | length 4.5
  Top Layer w0.12: SW2.4@110.255,159.475 SW2.3@112.795,159.475 112.775,159.495 R3.1@112.775,161.45
NetR10_1: R10.1 R15.1 U2.6 | length 4.5
  Top Layer w0.12: U2.6@33.575,155.4 33.575,155.225 33.9,154.9 R10.1@36.325,154.9 R15.1@36.325,153.475
NetR29_1: R29.1 U6.12 | length 1.7
  Top Layer w0.12: R29.1@23.3,114.125 23.3,114.85 23.55,115.1 U6.12@23.55,115.7
NetR32_2: R32.2 SB2.1 U8.7 | length 3.9
  Top Layer w0.12: SB2.1@19.25,108.65 19.26,108.64 19.55,108.64 ; R32.2@19.525,110.125 19.525,108.665 19.55,108.64 ; U8.7@21.7,108.64 19.55,108.64
NetR35_1: R35.1 R42.2 U10.1 | length 3.2
  Top Layer w0.12: U10.1@127.25,95.35 127.825,95.925 128.525,95.925 128.875,96.275 R42.2@129.1,96.275 R35.1@129.1,97.225
NetR36_2: R36.2 U12.A6 | length 4.3
  Top Layer w0.1: R36.2@74.15,96.525 74.15,93.946 U12.A6@75.4,92.696
NetR56_1: R56.1 R57.2 U18.5 | length 3.2
  Top Layer w0.12: R57.2@16.7,77.8 R56.1@18.3,77.8 ; U18.5@18.3,76.2 R56.1@18.3,77.8
NetR57_1: R57.1 RV3.3 | length 8.7
  Top Layer w0.12: RV3.3@7.794,75 10.594,77.8 R57.1@15.3,77.8
NetR59_1: R59.1 R60.2 U19.5 | length 2.7
  Top Layer w0.12: R60.2@45.3,76.7 R59.1@46.4,76.7 ; U19.5@46.4,75.1 R59.1@46.4,76.7
NetR66_2: R66.2 R103.1 U27.6 | length 133.4
  Top Layer w0.12: R103.1@37.825,34.4 v1(37.825,33.25) 38.075,33 U27.6@38.925,33 ; v1(100.925,65.45) 118.1,65.45 122.15,69.5 R66.2@124.2,69.5
  Signal Layer 2 w0.12: v1(99.55,25.375) 99.55,45.625 99.563,45.637 100.925,47 v1(100.925,65.45)
  Bottom Layer w0.102: v1(37.825,33.25) 38.35,33.775 61.35,33.775 69.75,25.375 v1(99.55,25.375)
NetR70_2: R70.2 R113.1 U30.6 | length 130.1
  Top Layer w0.102: R113.1@37.825,30.075 v1(37.825,29.2) 38.2,28.825 U30.6@38.925,28.825
  Top Layer w0.12: v1(101.45,63.875) 120.15,63.875 122.55,66.275 R70.2@124.225,66.275
  Signal Layer 2 w0.12: v1(100.3,24.95) 100.3,45.825 101.45,46.975 v1(101.45,63.875)
  Bottom Layer w0.102: v1(37.825,29.2) 47.3,29.2 48,29.9 64.725,29.9 69.675,24.95 v1(100.3,24.95)
NetR76_1: R76.1 U21.1 | length 2.4
  Top Layer w0.13: R76.1@89.5,56.3 89.505,56.295 U21.1@89.505,53.931
NetR79_1: R79.1 U22.8 | length 2.5
  Top Layer w0.12: R79.1@129.125,55.725 129.8,55.725 130.225,55.3 U22.8@130.225,54.08
NetR89_1: R89.1 TP31.1 U21.27 | length 33.5
  Top Layer w0.12: v1(86.925,63.675) 91.175,63.675 92.5,65 TP31.1@92.5,68.7 ; R89.1@88.1,42.2 88.235,42.335 v1(88.235,43.125) U21.27@88.235,44.751
  Signal Layer 2 w0.12: v1(86.925,63.675) 86.925,56.225 88.235,54.915 v1(88.235,43.125)
NetR90_1: R90.1 TP32.1 U21.28 | length 34.3
  Top Layer w0.12: v1(87.575,63) 92.1,63 94.1,65 TP32.1@94.1,68.7 ; U21.28@89.505,44.751 v1(89.505,43.125) 89.505,42.295 R90.1@89.6,42.2
  Signal Layer 2 w0.12: v1(87.575,63) 87.575,56.45 89.505,54.52 v1(89.505,43.125)
NetR92_1: R92.1 X3.1 | length 1.4
  Top Layer w0.1: R92.1@24.7,40.95 X3.1@26.15,40.95
NetR94_2: R94.2 R95.1 U21.18 | length 7.1
  Top Layer w0.13: U21.18@76.805,44.751 76.805,43.13 76.2,42.525 R94.2@76.2,39.1 R95.1@77.4,39.1
NetR96_2: R96.2 U26.L4 | length 4.3
  Top Layer w0.1: R96.2@23.275,37.25 23.475,37.25 24.475,36.25 24.475,34.05 U26.L4@24.8,33.725
NetR97_1: R97.1 X3.3 | length 1.2
  Top Layer w0.1: R97.1@27.4,38.075 X3.3@27.4,39.3
NetR97_2: R97.2 U26.G1 | length 1.5
  Top Layer w0.1: U26.G1@27.4,35.675 R97.2@27.4,37.175
NetR100_1: R100.1 R101.1 U26.N3 | length 4
  Top Layer w0.1: R100.1@20.675,35.8 R101.1@20.675,34.75 20.725,34.7 23.175,34.7 U26.N3@23.5,34.375
NetR102_1: R102.1 U25.4 | length 2.7
  Top Layer w0.12: R102.1@120.8,34.7 121.15,34.7 U25.4@121.15,37.075
NetR108_1: R108.1 R112.2 U29.6 | length 2.9
  Top Layer w0.12: U29.6@143.1,31.155 144.645,31.155 R112.2@144.9,30.9 R108.1@144.9,31.9
NetR109_2: R109.2 R112.1 U29.5 U29.8 | length 10.1
  Top Layer w0.12: U29.5@143.1,30.505 143.295,30.505 144.075,29.725 144.675,29.725 R112.1@144.9,29.5 145.675,29.5 145.925,29.75 145.925,31.475 146.5,32.05 R109.2@146.5,32.455 ; U29.8@143.1,32.455 146.705,32.455 146.825,32.575 R109.2@146.9,32.575
NetR110_1: R110.1 U27.7 | length 1.4
  Top Layer w0.12: R110.1@37.75,32 37.75,32.1 38.15,32.5 U27.7@38.925,32.5
NetR115_2: R115.2 U26.J15 | length 1.9
  Top Layer w0.09: U26.J15@26.1,26.575 26.1,25.675 26.725,25.05 R115.2@26.8,25.05
NetR116_1: R116.1 U26.F15 | length 3.4
  Top Layer w0.09: U26.F15@28.05,26.575 28.05,25.725 28.725,25.05 R116.1@30.35,25.05
NetR120_2: R120.2 U35.10 | length 2.3
  Top Layer w0.12: R120.2@112.65,17.325 112.675,17.35 U35.10@112.675,19.575
NetR121_2: R121.2 U35.12 | length 2.5
  Top Layer w0.12: U35.12@113.575,19.575 113.575,18.475 114.1,17.95 R121.2@114.1,17.325
NetR127_1: R127.1 SW3.3 SW3.4 | length 5.9
  Top Layer w0.12: SW3.4@132.53,11.725 SW3.3@135.07,11.725 R127.1@138.425,11.725
NetR141_2: R141.2 R142.1 U42.11 | length 4.4
  Bottom Layer w0.12: U42.11@35.4,151.5 35.4,151.875 35.8,152.275 36.915,152.275 37.215,151.975 R141.2@37.7,151.975 R142.1@37.7,150.55
NetR201_2: R201.2 U47.A5 | length 2.2
  Bottom Layer w0.12: U47.A5@128.784,95.346 130.909,95.346 R201.2@130.934,95.371
NetR212_1: R212.1 U47.A3 | length 3.1
  Bottom Layer w0.12: R212.1@126.734,92.271 126.784,92.321 U47.A3@126.784,95.346
NetR234_2: R234.2 U15.44 | length 6.4
  Top Layer w0.2: v1(39.225,84.75) U15.44@40.248,84.75
  Bottom Layer w0.2: v1(39.225,84.75) 39.748,84.75 40.248,84.25 40.248,83 41.123,82.125 R234.2@42.8,82.125
NetR248_1: R248.1 U49.6 | length 2.3
  Top Layer w0.12: U49.6@8.471,47.177 9.278,47.177 9.81,47.709 R248.1@10.558,47.709
NetR249_1: R249.1 R250.2 U49.2 | length 4.1
  Top Layer w0.12: R249.1@3.723,47.831 3.723,48.84 R250.2@3.771,48.888 ; R249.1@3.737,47.814 3.874,47.677 U49.2@6.671,47.677
NetR251_2: R251.2 U49.7 | length 2.8
  Top Layer w0.12: U49.7@8.471,47.677 8.975,47.677 10.038,48.74 10.304,48.74 10.564,49 R251.2@10.564,49.162
NetSB113_1: SB113.1 U15.41 | length 2.3
  Top Layer w0.2: v1(39.2,83.25) U15.41@40.248,83.25
  Bottom Layer w0.2: SB113.1@37.9,83.25 v1(39.2,83.25)
NetSB129_1: SB129.1 U35.2 | length 3
  Top Layer w0.12: U35.2@113.125,22.425 113.125,23.075 113.75,23.7 v1(114.15,23.7)
  Bottom Layer w0.12: v1(114.15,23.7) SB129.1@114.15,24.725
NetSB130_1: SB130.1 U35.3 | length 2.3
  Top Layer w0.12: U35.3@112.675,22.425 112.675,23.2 112.725,23.25 v1(112.725,23.7)
  Bottom Layer w0.12: v1(112.725,23.7) SB130.1@112.725,24.725
NetSB131_1: SB131.1 U35.4 | length 3.5
  Top Layer w0.12: v1(110.95,23.525) 111.9,23.525 112.225,23.2 U35.4@112.225,22.425
  Bottom Layer w0.12: v1(110.95,23.525) 110.95,24.4 SB131.1@111.275,24.725
NetSB132_1: SB132.1 U35.5 | length 3.8
  Top Layer w0.12: v1(110.075,23.575) 110.53,23.12 111.655,23.12 111.775,23 U35.5@111.775,22.425
  Bottom Layer w0.12: SB132.1@109.85,24.725 110.075,24.5 v1(110.075,23.575)
NetSB134_1: SB134.1 U37.1 | length 3.4
  Top Layer w0.12: U37.1@129.7,17.275 129.7,17.625 130.175,18.1 v1(131.575,18.1)
  Bottom Layer w0.12: v1(131.575,18.1) SB134.1@132.6,18.1
NetSB135_1: SB135.1 U37.4 | length 3.3
  Top Layer w0.12: v1(126.625,18.1) 127.75,18.1 128.5,17.35 U37.4@128.5,17.275
  Bottom Layer w0.12: SB135.1@125.6,18.1 v1(126.625,18.1)
NetSB144_1: SB144.1 U37.15 | length 2.3
  Top Layer w0.12: U37.15@130.275,16.7 130.875,16.7 130.925,16.65 v1(131.575,16.65)
  Bottom Layer w0.12: v1(131.575,16.65) SB144.1@132.6,16.65
NetSB145_1: SB145.1 U37.6 | length 2.3
  Top Layer w0.12: v1(126.625,16.65) 127.275,16.65 127.325,16.7 U37.6@127.925,16.7
  Bottom Layer w0.12: SB145.1@125.6,16.65 v1(126.625,16.65)
NetSB146_1: SB146.1 U37.14 | length 3.1
  Top Layer w0.12: U37.14@130.275,16.3 131.025,16.3 131.575,15.75 v1(131.575,15.225)
  Bottom Layer w0.12: v1(131.575,15.225) SB146.1@132.6,15.225
NetSB147_1: SB147.1 U37.9 | length 3.1
  Top Layer w0.12: v1(126.625,15.225) 128.05,15.225 128.5,15.675 U37.9@128.5,15.725
  Bottom Layer w0.12: SB147.1@125.6,15.225 v1(126.625,15.225)
NetTP14_1: TP14.1 U5.H5 | length 19.5
  Top Layer w0.08: v3(77.5,127) v2(77.75,126.75)
  Top Layer w0.12: v1(77.925,110.85) 77.925,109.975 TP14.1@78.75,109.15
  Signal Layer 1 w0.08: v3(77.5,127) v2(77.75,126.75)
  Signal Layer 2 w0.08: v3(77.5,127) 77.5,126.45 77.55,126.4 77.55,122.725
  Signal Layer 2 w0.1: 77.55,122.725 77.275,122.45 77.275,119.148 77.623,118.8 78.13,118.293
  Signal Layer 2 w0.12: v1(77.925,110.85) 77.925,116.53 78.13,116.735 78.13,118.293
NetTP17_1: TP17.1 U47.C5 | length 10.6
  Top Layer w0.12: v1(130.55,97.75) 135.025,97.75 135.816,96.959 TP17.1@138.86,96.959
  Bottom Layer w0.12: U47.C5@128.784,97.346 129.188,97.75 v1(130.55,97.75)
NetTP25_1: TP25.1 U18.3 | length 2.5
  Top Layer w0.2: U18.3@19.25,73.6 19.25,72.525 19.675,72.1 TP25.1@20.5,72.1
NetTP27_1: TP27.1 U19.3 | length 2.5
  Top Layer w0.12: U19.3@47.35,72.5 47.35,71.475 47.825,71 TP27.1@48.6,71
NRST: B2.1 B2.2 C147.2 CN13.10 CN18.12 D3.2 JP34.1 R53.2 R69.1 R120.1 R156.1 R211.1 SB64.1 U5.H3 U40.1 | length 433.4
  Top Layer w0.08: 76.994,118.8 76.994,122.574 77.569,123.149 77.569,123.506 77.25,123.825 77.25,125.75 U5.H3@77.5,126
  Top Layer w0.102: 76.994,118.8 76.994,117.923 v1(77.273,117.644)
  Top Layer w0.15: v1(32.2,93.8) D3.2@33.23,93.8 ; JP34.1@35.57,12.1 33.97,10.5 32.09,10.5 31.402,11.187 U40.1@30.4,11.187 28.737,11.187 27.85,10.3 B2.1@27.85,8.65 B2.2@37.35,8.65 ; v1(112.65,12.95) 113.9,14.2 113.9,14.825 112.8,15.925 R120.1@112.65,15.925 ; R69.1@125.125,67.35 v1(126.55,67.35) ; CN18.12@132.018,91.765 132.258,91.525 133.6,91.525 v1(133.8,91.325) ; v1(132.525,81.25) R53.2@134.35,81.25 ; CN13.10@133.34,101.185 132.8,100.645 132.8,99.426 133.276,98.95 v1(136.15,98.95)
  Signal Layer 2 w0.12: 132.525,73.325 132.725,73.525 132.725,74.675 132.525,74.875 132.525,80.5
  Signal Layer 2 w0.15: v1(32.2,93.8) 33.497,95.097 33.497,108.072 v1(34.325,108.9) ; v1(48.275,111.8) 51.075,114.6 v1(51.075,118.2) ; v1(124.6,12.65) 124.58,12.67 124.58,38.33 125.8,39.55 125.8,62.405 126.645,63.25 126.645,63.268 126.675,63.298 126.675,64.4 126.55,64.525 v1(126.55,67.35) ; v1(132.525,67.35) 132.525,73.325 ; 132.525,80.5 v1(132.525,81.25) 132.525,90.05 v1(133.8,91.325) 134.2,91.325 134.9,92.025 134.9,95.725 136.15,96.975 v1(136.15,98.95) 136.15,100.165 136.925,100.94 136.925,106.875 136.15,107.65 136.15,115.65 140.83,120.33 v1(140.83,126.5)
  Bottom Layer w0.12: 35.8,108.9 36.5,109.6 36.5,110.965 37.56,112.025 48.05,112.025 v1(48.275,111.8) ; 105.9,113.675 108.7,110.875 112.893,110.875 113.47,111.451 120.601,111.451 121.338,112.189 124.162,112.189 124.675,111.675 ; R156.1@110.4,126 111.525,126 112.125,125.4 115.76,125.4 116.797,126.437 121.662,126.437 122.219,126.995 126.43,126.995 126.925,126.5 132.283,126.5 ; 131.2,123.025 132.283,124.108 132.283,126.5 ; v1(140.83,126.5) 132.283,126.5
  Bottom Layer w0.15: v1(34.325,108.9) 35.8,108.9 ; JP34.1@35.57,12.1 39.825,12.1 41.65,13.925 100.175,13.925 101.15,12.95 v1(112.65,12.95) 112.9,13.2 115.6,13.2 116.15,12.65 v1(124.6,12.65) ; v1(51.075,118.2) 61.213,118.2 61.541,117.872 70.454,117.872 70.524,117.942 74.292,117.942 74.474,118.124 75.794,118.124 76.273,117.644 v1(77.273,117.644) ; C147.2@77.275,119.55 77.275,117.647 v1(77.273,117.644) ; 105.9,113.675 102.891,116.685 87.26,116.685 86.85,116.275 80.899,116.275 79.754,117.42 78.259,117.42 78.035,117.644 v1(77.273,117.644) ; 124.675,111.675 125.227,111.123 135.857,111.123 v1(136.154,111.419) ; v1(126.55,67.35) v1(132.525,67.35) ; R211.1@128.209,90.871 133.346,90.871 v1(133.8,91.325)
OCTOSPI_1_CLK_N: CN11.15 SB47.2 | length 23.8
  Top Layer w0.13: CN11.15@128.65,126.525 128.65,127.475 v1(128.875,127.7)
  Bottom Layer w0.13: SB47.2@110.1,131.15 110.165,131.085 110.253,131.085 111.057,130.281 111.583,130.281 112.267,129.597 112.267,129.595 112.507,129.355 112.509,129.355 113.214,128.65 115.714,128.65 116.714,127.65 120.35,127.65 122.406,129.706 127.908,129.706 128.406,129.208 128.406,128.169 v1(128.875,127.7)
OCTOSPI_1_CLK_P: CN11.17 R150.2 | length 23
  Top Layer w0.13: v1(127.625,127.7) 127.85,127.475 CN11.17@127.85,126.525
  Bottom Layer w0.13: R150.2@109.9,129.9 111.425,129.9 111.886,129.439 111.886,129.437 112.349,128.974 112.351,128.974 113.056,128.269 115.556,128.269 116.556,127.269 120.508,127.269 122.564,129.325 127.75,129.325 128.025,129.05 128.025,128.1 v1(127.625,127.7)
OCTOSPI_1_DQS: CN11.11 R148.2 | length 16.4
  Top Layer w0.1: CN11.11@130.25,126.525 v1(130.25,131.05)
  Bottom Layer w0.1: R148.2@118.375,131.05 v1(130.25,131.05)
OCTOSPI_1_IO0: CN11.3 R155.2 | length 20.9
  Top Layer w0.1: CN11.3@133.45,126.525 v1(133.45,127.825)
  Bottom Layer w0.1: R155.2@115.05,125.95 115.725,125.95 116.626,126.851 121.491,126.851 122.048,127.408 126.602,127.408 127.096,126.914 132.539,126.914 v1(133.45,127.825)
OCTOSPI_1_IO1: CN11.5 R152.2 | length 19
  Top Layer w0.1: CN11.5@132.65,126.525 v1(132.65,130.475)
  Bottom Layer w0.1: R152.2@118.375,128.5 119.95,128.5 121.6,130.15 132.325,130.15 v1(132.65,130.475)
OCTOSPI_1_IO2: CN11.7 R159.2 | length 20.1
  Top Layer w0.1: v1(131.85,124.375) CN11.7@131.85,126.525
  Bottom Layer w0.1: R159.2@114.85,122.625 115.41,122.625 116.352,123.567 123.527,123.567 124.628,124.668 130.279,124.668 130.572,124.375 v1(131.85,124.375)
OCTOSPI_1_IO3: CN11.9 R158.2 | length 14.5
  Top Layer w0.1: v1(131.05,124.792) CN11.9@131.05,126.525
  Bottom Layer w0.1: R158.2@118.625,124.425 122.775,124.425 123.375,125.025 130.817,125.025 v1(131.05,124.792)
OCTOSPI_1_IO4: CN11.8 R163.2 | length 15
  Top Layer w0.1: v1(131.85,120.387) CN11.8@131.85,122.025
  Bottom Layer w0.1: R163.2@118.625,120.625 121.6,120.625 121.838,120.387 v1(131.85,120.387)
OCTOSPI_1_IO5: CN11.10 R162.2 | length 24.2
  Top Layer w0.1: v1(127.7,119.475) 129.952,119.475 131.05,120.573 CN11.10@131.05,122.025
  Bottom Layer w0.1: R162.2@109.7,120.875 111.167,120.875 112.992,119.05 116.2,119.05 116.625,119.475 v1(127.7,119.475)
OCTOSPI_1_IO6: CN11.12 R164.2 | length 17.2
  Top Layer w0.1: v1(128.622,119.892) 129.409,119.892 130.25,120.733 CN11.12@130.25,122.025
  Bottom Layer w0.1: R164.2@114.817,119.716 114.817,119.892 v1(128.622,119.892)
OCTOSPI_1_IO7: CN11.14 R160.2 | length 22.9
  Top Layer w0.1: CN11.14@129.45,122 CN11.14@129.45,122.025 v1(129.45,123.958)
  Bottom Layer w0.1: R160.2@109.7,122.15 112.95,122.15 113.15,121.95 115.325,121.95 116.525,123.15 123.7,123.15 124.861,124.311 129.097,124.311 v1(129.45,123.958)
OCTOSPI_1_NCS: CN11.6 R24.1 R151.2 | length 31.1
  Top Layer w0.1: R24.1@132.725,120.3 132.65,120.375 CN11.6@132.65,122.025 132.65,124.3 v1(133.475,125.125)
  Signal Layer 2 w0.09: v1(133.475,125.125) 133.925,125.575 133.925,129.383 133.55,129.758 v1(133.55,131.225)
  Bottom Layer w0.1: R151.2@114.75,129.75 115.25,129.75 116,130.5 120.725,130.5 120.792,130.567 131.467,130.567 132.125,131.225 v1(133.55,131.225)
OCTOSPI_1_RST: CN11.16 SB64.2 | length 3.5
  Top Layer w0.12: v1(127.746,123.196) 128.279,123.196 128.65,122.825 CN11.16@128.65,122.025
  Bottom Layer w0.12: v1(127.746,123.196) 129.389,123.196
OCTOSPI_2_CLK: R179.1 U47.B2 | length 14.6
  Bottom Layer w0.12: R179.1@119.125,104.15 119.125,96.952 119.49,96.588 120.087,96.588 120.925,95.75 125.188,95.75 U47.B2@125.784,96.346
OCTOSPI_2_DQS: R178.1 U47.C3 | length 12.7
  Bottom Layer w0.1: R178.1@120.2,104.15 120.2,102.986 119.6,102.386 119.6,99.975 121.725,97.85 126.28,97.85 U47.C3@126.784,97.346
OCTOSPI_2_IO0: SB98.2 U47.D3 | length 6.6
  Bottom Layer w0.1: SB98.2@125.725,104.55 125.725,102.925 126.351,102.299 126.351,98.779 U47.D3@126.784,98.346
OCTOSPI_2_IO1: SB101.2 U47.D2 | length 9.4
  Bottom Layer w0.1: SB101.2@121.425,104.55 121.425,103.55 121.875,103.1 123.69,103.1 124.302,102.488 124.302,99.238 124.761,98.779 125.351,98.779 U47.D2@125.784,98.346
OCTOSPI_2_IO2: R177.1 U47.C4 | length 7.7
  Bottom Layer w0.1: U47.C4@127.784,97.346 128.275,97.837 128.275,99.825 129.875,101.425 R177.1@129.875,104.15
OCTOSPI_2_IO3: SB96.2 U47.D4 | length 7
  Bottom Layer w0.1: U47.D4@127.784,98.346 127.217,98.912 127.217,102.617 128.275,103.675 128.275,104.225 SB96.2@128.6,104.55
OCTOSPI_2_IO4: SB95.2 U47.D5 | length 8.7
  Bottom Layer w0.1: U47.D5@128.784,98.346 131.046,98.346 131.4,98.7 131.4,102.785 131.15,103.035 SB95.2@131.15,104.55
OCTOSPI_2_IO5: SB97.2 U47.E3 | length 5.4
  Bottom Layer w0.1: U47.E3@126.784,99.346 126.784,104.184 SB97.2@127.15,104.55
OCTOSPI_2_IO6: SB99.2 U47.E2 | length 5.8
  Bottom Layer w0.1: SB99.2@124.275,104.55 124.275,103.765 125.784,102.256 U47.E2@125.784,99.346
OCTOSPI_2_IO7: SB100.2 U47.E1 | length 6.8
  Bottom Layer w0.1: SB100.2@122.85,104.55 122.85,103.8 123.15,103.5 123.95,103.5 125.144,102.306 125.144,99.706 U47.E1@124.784,99.346
OCTOSPI_2_NCS: JP20.2 R212.2 SB112.2 | length 37.7
  Signal Layer 2 w0.12: JP20.2@121.45,108.325 122.425,107.35 122.425,102.617 123.701,101.341 123.701,99.859 123.466,99.624 123.19,99.348 123.3,99.238 v1(123.3,90.4)
  Bottom Layer w0.12: SB112.2@109.825,89.925 109.825,90.7 110.35,91.225 120.55,91.225 121.375,90.4 v1(123.3,90.4) 126.038,90.4 126.509,90.871 R212.2@126.734,90.871 R212.2@126.613,90.75
OCTOSPI_2_RST: R211.2 U47.A4 | length 3.3
  Bottom Layer w0.12: U47.A4@127.784,95.346 127.784,93.391 128.209,92.966 R211.2@128.209,92.271
OCTOSPI_3_NCS: CN11.1 JP20.3 R23.1 | length 43.1
  Top Layer w0.12: CN11.1@134.25,126.525 R23.1@134.25,128.675 ; R23.1@134.275,128.7 R23.1@134.25,128.675 ; v1(142.475,126.075) 138.7,126.075 137.4,127.375 136.1,128.675 R23.1@134.25,128.675
  Signal Layer 2 w0.12: v1(136.7,110.425) 136.7,115.6 142.475,121.375 v1(142.475,126.075)
  Bottom Layer w0.12: JP20.3@123.99,108.325 125.425,108.325 127.525,110.425 v1(136.7,110.425)
OPAMP1_INM: R43.2 R44.2 RV2.1 TP15.1 U5.M1 | length 111.7
  Top Layer w0.08: U5.M1@79.5,125 79.5,124.65 79.673,124.477 80.397,124.477 80.875,123.998 80.875,119.6 80.875,118.8
  Top Layer w0.12: RV2.1@5.25,94 7.8,94 8,94.2 R43.2@8,95.3 8,95.5 8.875,96.375 v1(20.69,96.375) ; v1(23.075,111.9) 24.05,111.9 24.425,112.275 56,112.275 58.85,109.425 69.3,109.425 69.75,109.875 75.35,109.875 76.755,108.47 79.295,108.47 79.95,109.125 TP15.1@80.75,109.125 82.175,110.55 82.175,117.335 80.875,118.635 80.875,118.8
  Signal Layer 2 w0.12: v1(20.69,96.375) 20.69,106.674 23.075,109.059 v1(23.075,111.9)
OPAMP1_INP: R39.2 SB68.2 | length 54.5
  Top Layer w0.12: R39.2@14.2,97.5 v1(15.25,97.5) ; v1(17.525,120) 18.29,120.765 22.674,120.765 23.234,121.325 24.1,121.325 24.31,121.115 32.442,121.115 33.852,122.525 v1(34.325,122.525)
  Signal Layer 2 w0.12: v1(15.25,97.5) 15.25,109.2 17.525,111.475 v1(17.525,120)
  Bottom Layer w0.12: v1(34.325,122.525) 34.525,122.325 37.55,122.325 38.355,121.52 39.27,121.52 39.45,121.7 42.625,121.7 43.045,121.28 45.45,121.28 SB68.2@45.45,121.1
OPAMP1_VOUT: RV2.2 RV2.3 SB53.2 TP18.1 | length 161.1
  Top Layer w0.12: TP18.1@3,91.4 3,93.95 RV2.3@2.95,94 2.95,95.45 4.1,96.6 RV2.2@4.1,98
  Signal Layer 2 w0.12: v1(109.949,92.799) 109.949,103.345 110.524,103.92 110.524,113.683 110.359,113.847 110.359,116.909 111.875,118.425 111.875,126.95 v1(111.55,127.275)
  Bottom Layer w0.1: 71.225,86.295 73.93,86.295 75.375,84.85
  Bottom Layer w0.12: v1(3,92.375) 5.9,89.475 45.789,89.475 48.978,86.287 70.921,86.287 70.93,86.295 71.225,86.295 ; 75.375,84.85 76.988,83.237 85.912,83.237 88.7,86.025 103.025,86.025 103.6,86.6 103.6,90.475 105.924,92.799 v1(109.949,92.799) ; SB53.2@110.1,127.4 110.225,127.275 v1(111.55,127.275)
OSC32_IN: C30.1 R27.2 X2.2 | length 2.1
  Top Layer w0.12: R27.2@73,115.425 73.125,115.3 C30.1@73.125,114.6 X2.2@73.125,113.4
OSC32_OUT: C31.1 R28.2 X2.1 | length 2.1
  Top Layer w0.12: X2.1@74.325,113.4 C31.1@74.325,114.6 74.325,115.3 R28.2@74.45,115.425
OSC_IN: C28.1 R25.2 X1.1 | length 3.6
  Top Layer w0.12: R25.2@77.725,115.525 77.475,115.525 77.475,114.775 C28.1@77.325,114.625 77.325,113.275 78.05,112.55 X1.1@78.1,112.55
OSC_OUT: C29.1 R26.2 X1.3 | length 2
  Top Layer w0.12: R26.2@79.225,115.525 C29.1@79.225,114.625 79.225,113.825 X1.3@79.45,113.6
PA0: CN9.42 SB65.1 SB68.1 SB72.1 SB79.1 U5.K3 | length 73.3
  Top Layer w0.08: U5.K3@78.5,126 v2(78.75,125.75)
  Top Layer w0.1: v1(78,119.575) 78.475,119.575 79.122,118.928 79.122,118.8
  Top Layer w0.12: CN9.42@46.043,119.605 46.113,119.675 v1(48.95,119.675) ; 79.122,118.8 79.122,118.629 80.792,116.959 80.792,112.871 81,112.663 81,111.05 v1(79.6,109.65)
  Signal Layer 1 w0.08: v1(78,119.575) 79.15,120.725 79.15,123.825 78.735,124.24 78.735,125.735 v2(78.75,125.75)
  Signal Layer 2 w0.12: v1(46.25,111.3) 50.005,115.055 50.005,118.62 v1(48.95,119.675)
  Bottom Layer w0.12: v1(46.25,111.3) 47.9,109.65 v1(79.6,109.65) ; SB79.1@46.55,118.25 SB72.1@46.55,119.675 ; SB65.1@46.55,122.55 SB68.1@46.55,121.1 SB72.1@46.55,119.675 ; SB72.1@46.575,119.7 SB72.1@46.55,119.675 ; v1(48.95,119.675) SB72.1@46.55,119.675
PA1: CN9.43 SB67.1 SB71.1 SB78.1 U5.L3 | length 73
  Top Layer w0.08: U5.L3@79,126 v2(79.25,125.75)
  Top Layer w0.127: CN9.43@40.943,118.335 v1(42.889,118.335)
  Signal Layer 1 w0.08: v1(78.3,118.8) 79.4,119.9 79.4,123.925 78.9,124.425 78.9,125.4 v2(79.25,125.75)
  Signal Layer 2 w0.12: v1(42.6,111.4) 42.6,114.738 42.47,114.868 42.47,117.916 v1(42.889,118.335) ; v1(76.811,109.164) 78.428,110.78 78.428,118.45 78.3,118.578 v1(78.3,118.8)
  Bottom Layer w0.12: SB78.1@36.512,118.35 SB71.1@36.512,119.8 ; SB67.1@36.512,121.225 SB71.1@36.512,119.8 ; v1(42.6,111.4) 45.272,111.4 45.777,110.895 46.28,110.895 47.82,109.355 76.62,109.355 v1(76.811,109.164) ; v1(42.889,118.335) 42.889,119.066 42.155,119.8 SB71.1@36.512,119.8
PA2: CN10.26 R151.1 SB48.1 U5.M2 | length 53.9
  Top Layer w0.08: U5.M2@79.5,125.5 79.75,125.25 79.75,125.104 79.75,124.896 79.75,124.858 79.967,124.642 80.645,124.642 81.04,124.247 81.04,120.897 81.238,120.7 81.238,119.312 81.75,118.8
  Top Layer w0.12: 81.75,118.8 82.65,117.9 v1(82.65,117.3) ; v1(101.525,129.125) 111.2,129.125 111.84,129.765 v1(112.677,129.765)
  Top Layer w0.127: v1(112.677,129.765) CN10.26@114.623,129.765
  Signal Layer 2 w0.12: v1(101.525,122.075) v1(101.525,129.125)
  Bottom Layer w0.12: v1(82.65,117.3) 82.948,117.002 95.314,117.002 100.387,122.075 v1(101.525,122.075) ; v1(112.677,129.765) 113.835,129.765 R151.1@113.85,129.75 113.85,130.975 SB48.1@113.925,131.05
PA3: CN10.25 R150.1 SB51.1 SB53.1 U5.N2 | length 64.1
  Top Layer w0.08: U5.N2@80,125.5 80.675,125.5 82.425,123.75 v1(82.425,122.55)
  Top Layer w0.13: v1(89.975,132.1) 88.075,132.1 87.95,132.225 87.95,132.5 88.075,132.625 91.125,132.625 91.225,132.725 91.225,133 91.075,133.15 88,133.15 87.875,133.275 87.875,133.45 88.025,133.6 91.1,133.6 91.225,133.725 91.225,133.975 91.1,134.1 90.175,134.1 90.025,134.25 90.025,134.415 90.175,134.565 98.146,134.565 102.502,130.209 107.132,130.209 v1(107.577,129.765) CN10.25@109.523,129.765
  Signal Layer 2 w0.104: v1(89.975,132.1) 89.975,130.599 91.16,129.413 91.16,127.558 91.5,127.218 91.5,123.35 90.65,122.5 v1(90.65,122.25)
  Bottom Layer w0.13: v1(82.425,122.55) 82.895,122.55 82.92,122.525 83.961,122.525 84.502,121.984 90.383,121.984 v1(90.65,122.25) ; v1(107.577,129.765) 108.865,129.765 R150.1@109,129.9 SB51.1@109,128.725 SB53.1@109,127.4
